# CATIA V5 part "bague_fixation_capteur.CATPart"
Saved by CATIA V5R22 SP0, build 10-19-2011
Part number: bague_fixation_capteur
Bounding box of the stored display mesh (mm): x 0 to 5, y -11.298 to 11.298, z -11.3 to 11.2
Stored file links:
  C:\Users\La forge\Desktop\CAO_PER_pick&place_2023A\Sous_Ensemble_Flacon\Verin\bague_fixation_capteur.CATPart
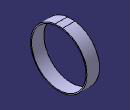
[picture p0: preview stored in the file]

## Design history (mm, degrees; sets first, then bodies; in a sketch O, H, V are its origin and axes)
Body1 (main body)
  Sketch1 on yz-plane, origin (0, 0, 0), H (0, 1, 0), V (0, 0, 1)
    arc A1 centre (0, 0) radius 10.9 from (-1.4731, 10.8) to (1.4731, 10.8) ccw
    point P1 (0.0378, -0.1964)
    line L1 (-1.4731, 10.8) -> (1.4731, 10.8)
    point P4 (2.5104, 5.0617)
    arc A2 centre (0, 0) radius 11.3 from (-1.5, 11.2) to (1.5, 11.2) ccw
    line L2 (1.5, 11.2) -> (-1.5, 11.2)
    radius A1 = 10.9
    distance A1 A2 = 0.4
    distance L1 L2 = 0.4
    distance L1 H = 10.8
    horizontal: L1 H, L2 H
  Pad1: profile Sketch1, direction (1, 0, 0), length 5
